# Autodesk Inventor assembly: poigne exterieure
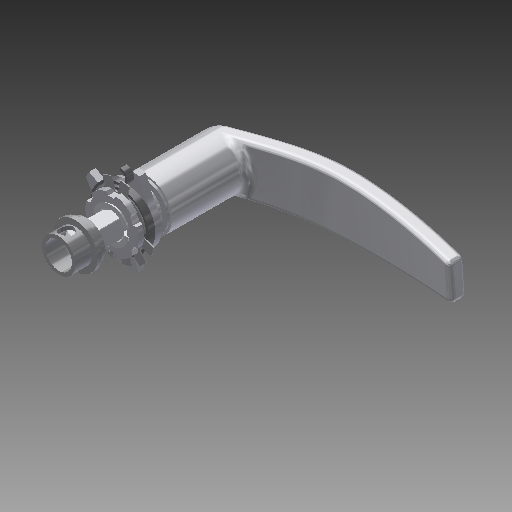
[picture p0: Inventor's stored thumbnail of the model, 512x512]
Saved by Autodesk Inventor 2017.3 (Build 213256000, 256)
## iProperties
Created: 2011-01
Part Number: poigne exterieure
Material: Générique
Document SubType Name: Assembly
Designer: ficho
Author: ficho
Sending System: SolidWorks 2009
Last Author: christophe
Last Saved: 2011-02-10
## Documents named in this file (9)
- G:\travail\année 2019-2020\réforme\toussaint\Serrure biométrique SET\Documentations_pedagogique\Modelisation_Solidworks\poigne exterieure.iam
- G:\travail\année 2019-2020\réforme\toussaint\Serrure biométrique SET\Documentations_pedagogique\Modelisation_Solidworks\pièce a3.ipt
- G:\travail\année 2019-2020\réforme\toussaint\Serrure biométrique SET\Documentations_pedagogique\Modelisation_Solidworks\bequille.ipt
- G:\travail\année 2019-2020\réforme\toussaint\Serrure biométrique SET\Documentations_pedagogique\Modelisation_Solidworks\pièce a16.ipt
- G:\travail\année 2019-2020\réforme\toussaint\Serrure biométrique SET\Documentations_pedagogique\Modelisation_Solidworks\pièce a5.ipt
- G:\travail\année 2019-2020\réforme\toussaint\Serrure biométrique SET\Documentations_pedagogique\Modelisation_Solidworks\pièce a7.ipt
- G:\travail\année 2019-2020\réforme\toussaint\Serrure biométrique SET\Documentations_pedagogique\Modelisation_Solidworks\pièce a4.ipt
- G:\travail\année 2019-2020\réforme\toussaint\Serrure biométrique SET\Documentations_pedagogique\Modelisation_Solidworks\Pièce16.ipt
- G:\travail\année 2019-2020\réforme\toussaint\Serrure biométrique SET\Documentations_pedagogique\Modelisation_Solidworks\carre.ipt
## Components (9 placed, 8 different names)
1. pièce a3:1
2. pièce a3:3
3. bequille:1
4. pièce a16:1
5. pièce a5:1
6. pièce a7:1
7. pièce a4:1
8. Pièce16:1
9. carre:1
